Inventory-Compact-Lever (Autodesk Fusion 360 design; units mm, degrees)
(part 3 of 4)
sketch "Restore cam service opening after obsolete bore closure" plane through (23.9, 0, 0) normal (1, 0, 0) x axis (0, 0, -1)
  line L1 (-42.2047, 46.7373) -> (-43.8497, 47.5044)
  line L2 (-40.5875, 45.9133) -> (-42.2047, 46.7373)
  line L3 (-39, 45.0333) -> (-40.5875, 45.9133)
  line L4 (-37.4442, 44.0985) -> (-39, 45.0333)
  line L5 (-35.922, 43.11) -> (-37.4442, 44.0985)
  line L6 (-34.4352, 42.0689) -> (-35.922, 43.11)
  line L7 (-32.9856, 40.9766) -> (-34.4352, 42.0689)
  line L8 (-31.575, 39.8343) -> (-32.9856, 40.9766)
  line L9 (-30.2052, 38.6435) -> (-31.575, 39.8343)
  line L10 (-28.8778, 37.4057) -> (-30.2052, 38.6435)
  line L11 (-27.5943, 36.1222) -> (-28.8778, 37.4057)
  line L12 (-26.3565, 34.7948) -> (-27.5943, 36.1222)
  line L13 (-25.1657, 33.425) -> (-26.3565, 34.7948)
  line L14 (-24.0234, 32.0144) -> (-25.1657, 33.425)
  line L15 (-22.9311, 30.5648) -> (-24.0234, 32.0144)
  line L16 (-21.89, 29.078) -> (-22.9311, 30.5648)
  line L17 (-20.9015, 27.5558) -> (-21.89, 29.078)
  line L18 (-19.9667, 26) -> (-20.9015, 27.5558)
  line L19 (-19.0867, 24.4125) -> (-19.9667, 26)
  line L20 (-18.2627, 22.7953) -> (-19.0867, 24.4125)
  line L21 (-17.4956, 21.1503) -> (-18.2627, 22.7953)
  line L22 (-16.7864, 19.4795) -> (-17.4956, 21.1503)
  line L23 (-16.136, 17.785) -> (-16.7864, 19.4795)
  line L24 (-15.5451, 16.0689) -> (-16.136, 17.785)
  line L25 (-15.0144, 14.3331) -> (-15.5451, 16.0689)
  line L26 (-14.5446, 12.5799) -> (-15.0144, 14.3331)
  line L27 (-14.1363, 10.8114) -> (-14.5446, 12.5799)
  line L28 (-13.79, 9.0297) -> (-14.1363, 10.8114)
  line L29 (-13.5061, 7.237) -> (-13.79, 9.0297)
  line L30 (-13.2849, 5.4355) -> (-13.5061, 7.237)
  line L31 (-13.1267, 3.6273) -> (-13.2849, 5.4355)
  line L32 (-13.0317, 1.8148) -> (-13.1267, 3.6273)
  line L33 (-13, 0) -> (-13.0317, 1.8148)
  line L34 (-13.0317, -1.8148) -> (-13, 0)
  line L35 (-13.1267, -3.6273) -> (-13.0317, -1.8148)
  line L36 (-13.2849, -5.4355) -> (-13.1267, -3.6273)
  line L37 (-13.5061, -7.237) -> (-13.2849, -5.4355)
  line L38 (-13.79, -9.0297) -> (-13.5061, -7.237)
  line L39 (-14.1363, -10.8114) -> (-13.79, -9.0297)
  line L40 (-14.5446, -12.5799) -> (-14.1363, -10.8114)
  line L41 (-15.0144, -14.3331) -> (-14.5446, -12.5799)
  line L42 (-15.5451, -16.0689) -> (-15.0144, -14.3331)
  line L43 (-16.136, -17.785) -> (-15.5451, -16.0689)
  line L44 (-16.7864, -19.4795) -> (-16.136, -17.785)
  line L45 (-17.4956, -21.1503) -> (-16.7864, -19.4795)
  line L46 (-18.2627, -22.7953) -> (-17.4956, -21.1503)
  line L47 (-19.0867, -24.4125) -> (-18.2627, -22.7953)
  line L48 (-19.9667, -26) -> (-19.0867, -24.4125)
  line L49 (-20.9015, -27.5558) -> (-19.9667, -26)
  line L50 (-21.89, -29.078) -> (-20.9015, -27.5558)
  line L51 (-22.9311, -30.5648) -> (-21.89, -29.078)
  line L52 (-24.0234, -32.0144) -> (-22.9311, -30.5648)
  line L53 (-25.1657, -33.425) -> (-24.0234, -32.0144)
  line L54 (-26.3565, -34.7948) -> (-25.1657, -33.425)
  line L55 (-27.5943, -36.1222) -> (-26.3565, -34.7948)
  line L56 (-28.8778, -37.4057) -> (-27.5943, -36.1222)
  line L57 (-30.2052, -38.6435) -> (-28.8778, -37.4057)
  line L58 (-31.575, -39.8343) -> (-30.2052, -38.6435)
  line L59 (-32.9856, -40.9766) -> (-31.575, -39.8343)
  line L60 (-34.4352, -42.0689) -> (-32.9856, -40.9766)
  line L61 (-35.922, -43.11) -> (-34.4352, -42.0689)
  line L62 (-37.4442, -44.0985) -> (-35.922, -43.11)
  line L63 (-39, -45.0333) -> (-37.4442, -44.0985)
  line L64 (-40.5875, -45.9133) -> (-39, -45.0333)
  line L65 (-42.2047, -46.7373) -> (-40.5875, -45.9133)
  line L66 (-43.8497, -47.5044) -> (-42.2047, -46.7373)
  line L67 (-54.4248, -23.7522) -> (-43.8497, -47.5044)
  line L68 (-53.6024, -23.3686) -> (-54.4248, -23.7522)
  line L69 (-52.7937, -22.9566) -> (-53.6024, -23.3686)
  line L70 (-52, -22.5167) -> (-52.7937, -22.9566)
  line L71 (-51.2221, -22.0493) -> (-52, -22.5167)
  line L72 (-50.461, -21.555) -> (-51.2221, -22.0493)
  line L73 (-49.7176, -21.0344) -> (-50.461, -21.555)
  line L74 (-48.9928, -20.4883) -> (-49.7176, -21.0344)
  line L75 (-48.2875, -19.9172) -> (-48.9928, -20.4883)
  line L76 (-47.6026, -19.3218) -> (-48.2875, -19.9172)
  line L77 (-46.9389, -18.7028) -> (-47.6026, -19.3218)
  line L78 (-46.2972, -18.0611) -> (-46.9389, -18.7028)
  line L79 (-45.6782, -17.3974) -> (-46.2972, -18.0611)
  line L80 (-45.0828, -16.7125) -> (-45.6782, -17.3974)
  line L81 (-44.5117, -16.0072) -> (-45.0828, -16.7125)
  line L82 (-43.9656, -15.2824) -> (-44.5117, -16.0072)
  line L83 (-43.445, -14.539) -> (-43.9656, -15.2824)
  line L84 (-42.9507, -13.7779) -> (-43.445, -14.539)
  line L85 (-42.4833, -13) -> (-42.9507, -13.7779)
  line L86 (-42.0434, -12.2063) -> (-42.4833, -13)
  line L87 (-41.6314, -11.3976) -> (-42.0434, -12.2063)
  line L88 (-41.2478, -10.5752) -> (-41.6314, -11.3976)
  line L89 (-40.8932, -9.7398) -> (-41.2478, -10.5752)
  line L90 (-40.568, -8.8925) -> (-40.8932, -9.7398)
  line L91 (-40.2725, -8.0344) -> (-40.568, -8.8925)
  line L92 (-40.0072, -7.1666) -> (-40.2725, -8.0344)
  line L93 (-39.7723, -6.29) -> (-40.0072, -7.1666)
  line L94 (-39.5682, -5.4057) -> (-39.7723, -6.29)
  line L95 (-39.395, -4.5149) -> (-39.5682, -5.4057)
  line L96 (-39.253, -3.6185) -> (-39.395, -4.5149)
  line L97 (-39.1424, -2.7177) -> (-39.253, -3.6185)
  line L98 (-39.0633, -1.8137) -> (-39.1424, -2.7177)
  line L99 (-39.0158, -0.9074) -> (-39.0633, -1.8137)
  line L100 (-39, 0) -> (-39.0158, -0.9074)
  line L101 (-39.0158, 0.9074) -> (-39, 0)
  line L102 (-39.0633, 1.8137) -> (-39.0158, 0.9074)
  line L103 (-39.1424, 2.7177) -> (-39.0633, 1.8137)
  line L104 (-39.253, 3.6185) -> (-39.1424, 2.7177)
  line L105 (-39.395, 4.5149) -> (-39.253, 3.6185)
  line L106 (-39.5682, 5.4057) -> (-39.395, 4.5149)
  line L107 (-39.7723, 6.29) -> (-39.5682, 5.4057)
  line L108 (-40.0072, 7.1666) -> (-39.7723, 6.29)
  line L109 (-40.2725, 8.0344) -> (-40.0072, 7.1666)
  line L110 (-40.568, 8.8925) -> (-40.2725, 8.0344)
  line L111 (-40.8932, 9.7398) -> (-40.568, 8.8925)
  line L112 (-41.2478, 10.5752) -> (-40.8932, 9.7398)
  line L113 (-41.6314, 11.3976) -> (-41.2478, 10.5752)
  line L114 (-42.0434, 12.2063) -> (-41.6314, 11.3976)
  line L115 (-42.4833, 13) -> (-42.0434, 12.2063)
  line L116 (-42.9507, 13.7779) -> (-42.4833, 13)
  line L117 (-43.445, 14.539) -> (-42.9507, 13.7779)
  line L118 (-43.9656, 15.2824) -> (-43.445, 14.539)
  line L119 (-44.5117, 16.0072) -> (-43.9656, 15.2824)
  line L120 (-45.0828, 16.7125) -> (-44.5117, 16.0072)
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extrude "Extrude47" cut sketch "Restore cam service opening after obsolete bore closure" along normal blind 12.2
work_plane "WorkPlane48" AlongDistance -15.4 ExtraOffset 0
sketch "Fill former M5 stop nut pocket" plane through (-15.4, 0, 0) normal (1, 0, 0) x axis (0, 0, -1)
  circle C1 centre (-79.6754, -33.9652) radius 4.9
extrude "Extrude48" add sketch "Fill former M5 stop nut pocket" along normal blind 6.4
work_plane "WorkPlane49" AlongDistance -36 ExtraOffset 0
sketch "Fill former M5 stop bore" plane through (-36, 0, 0) normal (1, 0, 0) x axis (0, 0, -1)
  circle C1 centre (-79.6754, -33.9652) radius 2.71
extrude "Extrude49" add sketch "Fill former M5 stop bore" along normal blind 27
work_plane "WorkPlane50" AlongDistance -36.1 ExtraOffset 0
sketch "M3 stop reinforcement bore" plane through (-36.1, 0, 0) normal (1, 0, 0) x axis (0, 0, -1)
  circle C1 centre (-79.6754, -33.9652) radius 1.7
extrude "Extrude50" cut sketch "M3 stop reinforcement bore" along normal blind 27.2
work_plane "WorkPlane51" AlongDistance -13.5 ExtraOffset 0
sketch "Captive M3 locknut stop pocket" plane through (-13.5, 0, 0) normal (1, 0, 0) x axis (0, 0, -1)
  line L1 (-82.5754, -32.2908) -> (-79.6754, -30.6165)
  line L2 (-82.5754, -35.6395) -> (-82.5754, -32.2908)
  line L3 (-79.6754, -37.3138) -> (-82.5754, -35.6395)
  line L4 (-76.7754, -35.6395) -> (-79.6754, -37.3138)
  line L5 (-76.7754, -32.2908) -> (-76.7754, -35.6395)
  line L6 (-79.6754, -30.6165) -> (-76.7754, -32.2908)
extrude "Extrude51" cut sketch "Captive M3 locknut stop pocket" along normal blind 4.6
work_plane "WorkPlane52" AlongDistance -15.4 ExtraOffset 0
sketch "Fill former M5 stop nut pocket (1)" plane through (-15.4, 0, 0) normal (1, 0, 0) x axis (0, 0, -1)
  circle C1 centre (-79.6754, 33.9652) radius 4.9
extrude "Extrude52" add sketch "Fill former M5 stop nut pocket (1)" along normal blind 6.4
work_plane "WorkPlane53" AlongDistance -36 ExtraOffset 0
sketch "Fill former M5 stop bore (1)" plane through (-36, 0, 0) normal (1, 0, 0) x axis (0, 0, -1)
  circle C1 centre (-79.6754, 33.9652) radius 2.71
extrude "Extrude53" add sketch "Fill former M5 stop bore (1)" along normal blind 27
work_plane "WorkPlane54" AlongDistance -36.1 ExtraOffset 0
sketch "M3 stop reinforcement bore (1)" plane through (-36.1, 0, 0) normal (1, 0, 0) x axis (0, 0, -1)
  circle C1 centre (-79.6754, 33.9652) radius 1.7
extrude "Extrude54" cut sketch "M3 stop reinforcement bore (1)" along normal blind 27.2
work_plane "WorkPlane55" AlongDistance -13.5 ExtraOffset 0
sketch "Captive M3 locknut stop pocket (1)" plane through (-13.5, 0, 0) normal (1, 0, 0) x axis (0, 0, -1)
  line L1 (-82.5754, 35.6395) -> (-79.6754, 37.3138)
  line L2 (-82.5754, 32.2908) -> (-82.5754, 35.6395)
  line L3 (-79.6754, 30.6165) -> (-82.5754, 32.2908)
  line L4 (-76.7754, 32.2908) -> (-79.6754, 30.6165)
  line L5 (-76.7754, 35.6395) -> (-76.7754, 32.2908)
  line L6 (-79.6754, 37.3138) -> (-76.7754, 35.6395)
extrude "Extrude55" cut sketch "Captive M3 locknut stop pocket (1)" along normal blind 4.6
work_plane "WorkPlane56" AlongDistance -17.5 ExtraOffset 0
sketch "Recess M3 locknut to keep bolt inside stop" plane through (-17.5, 0, 0) normal (1, 0, 0) x axis (0, 0, -1)
  line L1 (-82.5754, -32.2908) -> (-79.6754, -30.6165)
  line L2 (-82.5754, -35.6395) -> (-82.5754, -32.2908)
  line L3 (-79.6754, -37.3138) -> (-82.5754, -35.6395)
  line L4 (-76.7754, -35.6395) -> (-79.6754, -37.3138)
  line L5 (-76.7754, -32.2908) -> (-76.7754, -35.6395)
  line L6 (-79.6754, -30.6165) -> (-76.7754, -32.2908)
extrude "Extrude56" cut sketch "Recess M3 locknut to keep bolt inside stop" along normal blind 4.01
work_plane "WorkPlane57" AlongDistance -17.5 ExtraOffset 0
sketch "Recess M3 locknut to keep bolt inside stop (1)" plane through (-17.5, 0, 0) normal (1, 0, 0) x axis (0, 0, -1)
  line L1 (-82.5754, 35.6395) -> (-79.6754, 37.3138)
  line L2 (-82.5754, 32.2908) -> (-82.5754, 35.6395)
  line L3 (-79.6754, 30.6165) -> (-82.5754, 32.2908)
  line L4 (-76.7754, 32.2908) -> (-79.6754, 30.6165)
  line L5 (-76.7754, 35.6395) -> (-76.7754, 32.2908)
  line L6 (-79.6754, 37.3138) -> (-76.7754, 35.6395)
extrude "Extrude57" cut sketch "Recess M3 locknut to keep bolt inside stop (1)" along normal blind 4.01
work_plane "WorkPlane6" AlongDistance -7.2 ExtraOffset 0
sketch "Upright socket roof 45 degrees" plane through (0, -7.2, 0) normal (0, 1, 0) x axis (1, 0, 0)
  line L1 (-7.2, -196) -> (0, -196)
  line L2 (0, -203.2) -> (-7.2, -196)
  line L3 (0, -196) -> (0, -203.2)
extrude "Extrude5" cut sketch "Upright socket roof 45 degrees" along normal blind 14.4
work_plane "WorkPlane8" AlongDistance -7.2 ExtraOffset 0
sketch "Upright socket roof 45 degrees" plane through (0, -7.2, 0) normal (0, 1, 0) x axis (1, 0, 0)
  line L1 (7.2, -196) -> (0, -196)
  line L2 (0, -203.2) -> (7.2, -196)
  line L3 (0, -196) -> (0, -203.2)
extrude "Extrude7" cut sketch "Upright socket roof 45 degrees" along normal blind 14.4
work_plane "WorkPlane58" AlongDistance -36 ExtraOffset 0
sketch "Stock M5x14 mounting seat Z64" plane through (-36, 0, 0) normal (1, 0, 0) x axis (0, 0, -1)
  line L1 (-63, -70) -> (-63, -95)
  line L2 (-64, -70) -> (-63, -70)
  line L3 (-64, -95) -> (-64, -70)
  line L4 (-63, -95) -> (-64, -95)
extrude "Extrude58" add sketch "Stock M5x14 mounting seat Z64" along normal blind 12
work_plane "WorkPlane59" AlongDistance 62.9 ExtraOffset 0
sketch "Continue rail clearance through new seat" plane through (0, 0, 62.9) normal (0, 0, 1) x axis (1, 0, 0)
  circle C1 centre (-30, -85) radius 2.7
extrude "Extrude59" cut sketch "Continue rail clearance through new seat" along normal blind 1.2
work_plane "WorkPlane1" AlongDistance 50 ExtraOffset 0
sketch "Rail M5x14 DIN912 (-30, -1)" plane through (0, 0, 50) normal (0, 0, 1) x axis (1, 0, 0)
  circle C1 centre (-30, -85) radius 2.5
extrude "Extrude1" new body sketch "Rail M5x14 DIN912 (-30, -1)" along normal blind 14 bodies "HARDWARE Rail M5x14 DIN912 (-30, -1)"
work_plane "WorkPlane2" AlongDistance 64 ExtraOffset 0
sketch "Button head" plane through (0, 0, 64) normal (0, 0, 1) x axis (1, 0, 0)
  circle C1 centre (-30, -85) radius 4.25
extrude "Extrude2" add sketch "Button head" along normal blind 5
work_plane "WorkPlane60" AlongDistance -36 ExtraOffset 0
sketch "Stock M5x14 mounting seat Z64 (1)" plane through (-36, 0, 0) normal (1, 0, 0) x axis (0, 0, -1)
  line L1 (-63, 95) -> (-63, 70)
  line L2 (-64, 95) -> (-63, 95)
  line L3 (-64, 70) -> (-64, 95)
  line L4 (-63, 70) -> (-64, 70)
extrude "Extrude60" add sketch "Stock M5x14 mounting seat Z64 (1)" along normal blind 12
work_plane "WorkPlane61" AlongDistance 62.9 ExtraOffset 0
sketch "Continue rail clearance through new seat (1)" plane through (0, 0, 62.9) normal (0, 0, 1) x axis (1, 0, 0)
  circle C1 centre (-30, 85) radius 2.7
extrude "Extrude61" cut sketch "Continue rail clearance through new seat (1)" along normal blind 1.2
work_plane "WorkPlane1" AlongDistance 50 ExtraOffset 0
sketch "Rail M5x14 DIN912 (-30, 1)" plane through (0, 0, 50) normal (0, 0, 1) x axis (1, 0, 0)
  circle C1 centre (-30, 85) radius 2.5
extrude "Extrude1" new body sketch "Rail M5x14 DIN912 (-30, 1)" along normal blind 14 bodies "HARDWARE Rail M5x14 DIN912 (-30, 1)"
work_plane "WorkPlane2" AlongDistance 64 ExtraOffset 0
sketch "Button head" plane through (0, 0, 64) normal (0, 0, 1) x axis (1, 0, 0)
  circle C1 centre (-30, 85) radius 4.25
extrude "Extrude2" add sketch "Button head" along normal blind 5
work_plane "WorkPlane62" AlongDistance -36 ExtraOffset 0
sketch "Close obsolete long pivot screw hole" plane through (-36, 0, 0) normal (1, 0, 0) x axis (0, 0, -1)
  circle C1 centre (-12, -35) radius 1.71
extrude "Extrude62" add sketch "Close obsolete long pivot screw hole" along normal blind 12
work_plane "WorkPlane63" AlongDistance -26 ExtraOffset 0
sketch "Blind captive printed pivot seat" plane through (-26, 0, 0) normal (1, 0, 0) x axis (0, 0, -1)
  circle C1 centre (-12, -35) radius 4.15
extrude "Extrude63" cut sketch "Blind captive printed pivot seat" along normal blind 2.1
work_plane "WorkPlane48" AlongDistance 24 ExtraOffset 0
sketch "Stock M5x14 mounting seat Z64" plane through (24, 0, 0) normal (1, 0, 0) x axis (0, 0, -1)
  line L1 (-63, -70) -> (-63, -95)
  line L2 (-64, -70) -> (-63, -70)
  line L3 (-64, -95) -> (-64, -70)
  line L4 (-63, -95) -> (-64, -95)
extrude "Extrude48" add sketch "Stock M5x14 mounting seat Z64" along normal blind 12
work_plane "WorkPlane49" AlongDistance 62.9 ExtraOffset 0
sketch "Continue rail clearance through new seat" plane through (0, 0, 62.9) normal (0, 0, 1) x axis (1, 0, 0)
  circle C1 centre (30, -85) radius 2.7
extrude "Extrude49" cut sketch "Continue rail clearance through new seat" along normal blind 1.2
work_plane "WorkPlane1" AlongDistance 50 ExtraOffset 0
sketch "Rail M5x14 DIN912 (30, -1)" plane through (0, 0, 50) normal (0, 0, 1) x axis (1, 0, 0)
  circle C1 centre (30, -85) radius 2.5
extrude "Extrude1" new body sketch "Rail M5x14 DIN912 (30, -1)" along normal blind 14 bodies "HARDWARE Rail M5x14 DIN912 (30, -1)"
work_plane "WorkPlane2" AlongDistance 64 ExtraOffset 0
sketch "Button head" plane through (0, 0, 64) normal (0, 0, 1) x axis (1, 0, 0)
  circle C1 centre (30, -85) radius 4.25
extrude "Extrude2" add sketch "Button head" along normal blind 5
work_plane "WorkPlane50" AlongDistance 24 ExtraOffset 0
sketch "Stock M5x14 mounting seat Z64 (1)" plane through (24, 0, 0) normal (1, 0, 0) x axis (0, 0, -1)
  line L1 (-63, 95) -> (-63, 70)
  line L2 (-64, 95) -> (-63, 95)
  line L3 (-64, 70) -> (-64, 95)
  line L4 (-63, 70) -> (-64, 70)
extrude "Extrude50" add sketch "Stock M5x14 mounting seat Z64 (1)" along normal blind 12
work_plane "WorkPlane51" AlongDistance 62.9 ExtraOffset 0
sketch "Continue rail clearance through new seat (1)" plane through (0, 0, 62.9) normal (0, 0, 1) x axis (1, 0, 0)
  circle C1 centre (30, 85) radius 2.7
extrude "Extrude51" cut sketch "Continue rail clearance through new seat (1)" along normal blind 1.2
work_plane "WorkPlane1" AlongDistance 50 ExtraOffset 0
sketch "Rail M5x14 DIN912 (30, 1)" plane through (0, 0, 50) normal (0, 0, 1) x axis (1, 0, 0)
  circle C1 centre (30, 85) radius 2.5
extrude "Extrude1" new body sketch "Rail M5x14 DIN912 (30, 1)" along normal blind 14 bodies "HARDWARE Rail M5x14 DIN912 (30, 1)"
work_plane "WorkPlane2" AlongDistance 64 ExtraOffset 0
sketch "Button head" plane through (0, 0, 64) normal (0, 0, 1) x axis (1, 0, 0)
  circle C1 centre (30, 85) radius 4.25
extrude "Extrude2" add sketch "Button head" along normal blind 5
work_plane "WorkPlane52" AlongDistance 24 ExtraOffset 0
sketch "Close obsolete long pivot screw hole" plane through (24, 0, 0) normal (1, 0, 0) x axis (0, 0, -1)
  circle C1 centre (-12, -35) radius 1.71
extrude "Extrude52" add sketch "Close obsolete long pivot screw hole" along normal blind 12
work_plane "WorkPlane53" AlongDistance 23.9 ExtraOffset 0
sketch "Blind captive printed pivot seat" plane through (23.9, 0, 0) normal (1, 0, 0) x axis (0, 0, -1)
  circle C1 centre (-12, -35) radius 4.15
extrude "Extrude53" cut sketch "Blind captive printed pivot seat" along normal blind 2.1
work_plane "WorkPlane1" AlongDistance -25.85 ExtraOffset 0
sketch "Captured axle 0.3 mm total end clearance" plane through (-25.85, 0, 0) normal (1, 0, 0) x axis (0, 0, -1)
  circle C1 centre (-12, -35) radius 4
extrude "Extrude1" new body sketch "Captured axle 0.3 mm total end clearance" along normal blind 51.7 bodies "P25 Captured printed pivot lower half"
work_plane "WorkPlane2" AlongDistance -26 ExtraOffset 0
sketch "Longitudinal flat print face" plane through (-26, 0, 0) normal (1, 0, 0) x axis (0, 0, -1)
  line L1 (-7, -30) -> (-7, -35)
  line L2 (-17, -30) -> (-7, -30)
  line L3 (-17, -35) -> (-17, -30)
  line L4 (-7, -35) -> (-17, -35)
extrude "Extrude2" cut sketch "Longitudinal flat print face" along normal blind 52
work_plane "WorkPlane1" AlongDistance -25.85 ExtraOffset 0
sketch "Captured axle 0.3 mm total end clearance" plane through (-25.85, 0, 0) normal (1, 0, 0) x axis (0, 0, -1)
  circle C1 centre (-12, -35) radius 4
extrude "Extrude1" new body sketch "Captured axle 0.3 mm total end clearance" along normal blind 51.7 bodies "P26 Captured printed pivot upper half"
work_plane "WorkPlane2" AlongDistance -26 ExtraOffset 0
sketch "Longitudinal flat print face" plane through (-26, 0, 0) normal (1, 0, 0) x axis (0, 0, -1)
  line L1 (-7, -35) -> (-7, -40)
  line L2 (-17, -35) -> (-7, -35)
  line L3 (-17, -40) -> (-17, -35)
  line L4 (-7, -40) -> (-17, -40)
extrude "Extrude2" cut sketch "Longitudinal flat print face" along normal blind 52
work_plane "WorkPlane9" AlongDistance 9 ExtraOffset 0
sketch "Recess for stocked M3x20 grip screw" plane through (9, 0, 0) normal (1, 0, 0) x axis (0, 0, -1)
  circle C1 centre (-180, 0) radius 3.1
extrude "Extrude8" cut sketch "Recess for stocked M3x20 grip screw" along normal blind 3.6
work_plane "WorkPlane1" AlongDistance -11 ExtraOffset 0
sketch "Grip M3x20 cap head 180" plane through (-11, 0, 0) normal (1, 0, 0) x axis (0, 0, -1)
  circle C1 centre (-180, 0) radius 1.5
extrude "Extrude1" new body sketch "Grip M3x20 cap head 180" along normal blind 20 bodies "HARDWARE Grip M3x20 cap head 180"
work_plane "WorkPlane2" AlongDistance 9 ExtraOffset 0
sketch "Button head" plane through (9, 0, 0) normal (1, 0, 0) x axis (0, 0, -1)
  circle C1 centre (-180, 0) radius 2.75
extrude "Extrude2" add sketch "Button head" along normal blind 3
work_plane "WorkPlane10" AlongDistance 9 ExtraOffset 0
sketch "Recess for stocked M3x20 grip screw (1)" plane through (9, 0, 0) normal (1, 0, 0) x axis (0, 0, -1)
  circle C1 centre (-190, 0) radius 3.1
extrude "Extrude9" cut sketch "Recess for stocked M3x20 grip screw (1)" along normal blind 3.6
work_plane "WorkPlane1" AlongDistance -11 ExtraOffset 0
sketch "Grip M3x20 cap head 190" plane through (-11, 0, 0) normal (1, 0, 0) x axis (0, 0, -1)
  circle C1 centre (-190, 0) radius 1.5
extrude "Extrude1" new body sketch "Grip M3x20 cap head 190" along normal blind 20 bodies "HARDWARE Grip M3x20 cap head 190"
work_plane "WorkPlane2" AlongDistance 9 ExtraOffset 0
sketch "Button head" plane through (9, 0, 0) normal (1, 0, 0) x axis (0, 0, -1)
  circle C1 centre (-190, 0) radius 2.75
extrude "Extrude2" add sketch "Button head" along normal blind 3
work_plane "WorkPlane64" AlongDistance -36.1 ExtraOffset 0
sketch "Stock M3x20 stop recessed cap head" plane through (-36.1, 0, 0) normal (1, 0, 0) x axis (0, 0, -1)
  circle C1 centre (-79.6754, -33.9652) radius 3.1
extrude "Extrude64" cut sketch "Stock M3x20 stop recessed cap head" along normal blind 4.6
work_plane "WorkPlane1" AlongDistance -31.5 ExtraOffset 0
sketch "Stop M3x20 cap head -1" plane through (-31.5, 0, 0) normal (1, 0, 0) x axis (0, 0, -1)
  circle C1 centre (-79.6754, -33.9652) radius 1.5
extrude "Extrude1" new body sketch "Stop M3x20 cap head -1" along normal blind 20 bodies "HARDWARE Stop M3x20 cap head -1"
work_plane "WorkPlane2" AlongDistance -34.5 ExtraOffset 0
sketch "Button head" plane through (-34.5, 0, 0) normal (1, 0, 0) x axis (0, 0, -1)
  circle C1 centre (-79.6754, -33.9652) radius 2.75
extrude "Extrude2" add sketch "Button head" along normal blind 3
work_plane "WorkPlane1" AlongDistance -17.5 ExtraOffset 0
sketch "Stop M3 plain captive nut -1" plane through (-17.5, 0, 0) normal (1, 0, 0) x axis (0, 0, -1)
  line L1 (-82.4254, -32.3774) -> (-79.6754, -30.7897)
  line L2 (-82.4254, -35.5529) -> (-82.4254, -32.3774)
  line L3 (-79.6754, -37.1406) -> (-82.4254, -35.5529)
  line L4 (-76.9254, -35.5529) -> (-79.6754, -37.1406)
  line L5 (-76.9254, -32.3774) -> (-76.9254, -35.5529)
  line L6 (-79.6754, -30.7897) -> (-76.9254, -32.3774)
extrude "Extrude1" new body sketch "Stop M3 plain captive nut -1" along normal blind 2.4 bodies "HARDWARE Stop M3 plain captive nut -1"
work_plane "WorkPlane2" AlongDistance -17.6 ExtraOffset 0
sketch "Thread envelope" plane through (-17.6, 0, 0) normal (1, 0, 0) x axis (0, 0, -1)
  circle C1 centre (-79.6754, -33.9652) radius 1.5
extrude "Extrude2" cut sketch "Thread envelope" along normal blind 2.6
work_plane "WorkPlane65" AlongDistance -36.1 ExtraOffset 0
sketch "Stock M3x20 stop recessed cap head (1)" plane through (-36.1, 0, 0) normal (1, 0, 0) x axis (0, 0, -1)
  circle C1 centre (-79.6754, 33.9652) radius 3.1
extrude "Extrude65" cut sketch "Stock M3x20 stop recessed cap head (1)" along normal blind 4.6
work_plane "WorkPlane1" AlongDistance -31.5 ExtraOffset 0
sketch "Stop M3x20 cap head 1" plane through (-31.5, 0, 0) normal (1, 0, 0) x axis (0, 0, -1)
  circle C1 centre (-79.6754, 33.9652) radius 1.5
extrude "Extrude1" new body sketch "Stop M3x20 cap head 1" along normal blind 20 bodies "HARDWARE Stop M3x20 cap head 1"
work_plane "WorkPlane2" AlongDistance -34.5 ExtraOffset 0
sketch "Button head" plane through (-34.5, 0, 0) normal (1, 0, 0) x axis (0, 0, -1)
  circle C1 centre (-79.6754, 33.9652) radius 2.75
extrude "Extrude2" add sketch "Button head" along normal blind 3
work_plane "WorkPlane1" AlongDistance -17.5 ExtraOffset 0
sketch "Stop M3 plain captive nut 1" plane through (-17.5, 0, 0) normal (1, 0, 0) x axis (0, 0, -1)
  line L1 (-82.4254, 35.5529) -> (-79.6754, 37.1406)
  line L2 (-82.4254, 32.3774) -> (-82.4254, 35.5529)
  line L3 (-79.6754, 30.7897) -> (-82.4254, 32.3774)
  line L4 (-76.9254, 32.3774) -> (-79.6754, 30.7897)
  line L5 (-76.9254, 35.5529) -> (-76.9254, 32.3774)
  line L6 (-79.6754, 37.1406) -> (-76.9254, 35.5529)
extrude "Extrude1" new body sketch "Stop M3 plain captive nut 1" along normal blind 2.4 bodies "HARDWARE Stop M3 plain captive nut 1"
work_plane "WorkPlane2" AlongDistance -17.6 ExtraOffset 0
sketch "Thread envelope" plane through (-17.6, 0, 0) normal (1, 0, 0) x axis (0, 0, -1)
  circle C1 centre (-79.6754, 33.9652) radius 1.5
extrude "Extrude2" cut sketch "Thread envelope" along normal blind 2.6
work_plane "WorkPlane10" AlongDistance 7 ExtraOffset 0
sketch "Bearing inner race support pad" plane through (7, 0, 0) normal (1, 0, 0) x axis (0, 0, -1)
  circle C1 centre (-12, 0) radius 2.4
extrude "Extrude10" add sketch "Bearing inner race support pad" along normal blind 1
work_plane "WorkPlane11" AlongDistance 6.9 ExtraOffset 0
sketch "Preserve roller screw clearance" plane through (6.9, 0, 0) normal (1, 0, 0) x axis (0, 0, -1)
  circle C1 centre (-12, 0) radius 1.7
extrude "Extrude11" cut sketch "Preserve roller screw clearance" along normal blind 1.2
work_plane "WorkPlane12" AlongDistance 16 ExtraOffset 0
sketch "Bearing inner race support pad (1)" plane through (16, 0, 0) normal (1, 0, 0) x axis (0, 0, -1)
  circle C1 centre (-12, 0) radius 2.4
extrude "Extrude12" add sketch "Bearing inner race support pad (1)" along normal blind 1
work_plane "WorkPlane13" AlongDistance 15.9 ExtraOffset 0
sketch "Preserve roller screw clearance (1)" plane through (15.9, 0, 0) normal (1, 0, 0) x axis (0, 0, -1)
  circle C1 centre (-12, 0) radius 1.7
extrude "Extrude13" cut sketch "Preserve roller screw clearance (1)" along normal blind 1.2
work_plane "WorkPlane1" AlongDistance 8 ExtraOffset 0
sketch "Stock 623ZZ envelope 3x10x4" plane through (8, 0, 0) normal (1, 0, 0) x axis (0, 0, -1)
  circle C1 centre (-12, 0) radius 5
extrude "Extrude1" new body sketch "Stock 623ZZ envelope 3x10x4" along normal blind 4 bodies "HARDWARE 623ZZ roller bearing at 8"
work_plane "WorkPlane2" AlongDistance 7.9 ExtraOffset 0
sketch "Bearing inner race bore" plane through (7.9, 0, 0) normal (1, 0, 0) x axis (0, 0, -1)
  circle C1 centre (-12, 0) radius 1.5
extrude "Extrude2" cut sketch "Bearing inner race bore" along normal blind 4.2
work_plane "WorkPlane1" AlongDistance 12 ExtraOffset 0
sketch "Stock 623ZZ envelope 3x10x4" plane through (12, 0, 0) normal (1, 0, 0) x axis (0, 0, -1)
  circle C1 centre (-12, 0) radius 5
extrude "Extrude1" new body sketch "Stock 623ZZ envelope 3x10x4" along normal blind 4 bodies "HARDWARE 623ZZ roller bearing at 12"
work_plane "WorkPlane2" AlongDistance 11.9 ExtraOffset 0
sketch "Bearing inner race bore" plane through (11.9, 0, 0) normal (1, 0, 0) x axis (0, 0, -1)
  circle C1 centre (-12, 0) radius 1.5
extrude "Extrude2" cut sketch "Bearing inner race bore" along normal blind 4.2
work_plane "WorkPlane45" AlongDistance 38 ExtraOffset 0
sketch "Close former long guide bore" plane through (0, 0, 38) normal (0, 0, 1) x axis (1, 0, 0)
  circle C1 centre (5, -55) radius 1.71
extrude "Extrude45" add sketch "Close former long guide bore" along normal blind 21
work_plane "WorkPlane46" AlongDistance 38 ExtraOffset 0
sketch "Close former long guide bore (1)" plane through (0, 0, 38) normal (0, 0, 1) x axis (1, 0, 0)
  circle C1 centre (19, -55) radius 1.71
extrude "Extrude46" add sketch "Close former long guide bore (1)" along normal blind 21
work_plane "WorkPlane47" AlongDistance 38 ExtraOffset 0
sketch "Close obsolete M4 nut pocket" plane through (0, 0, 38) normal (0, 0, 1) x axis (1, 0, 0)
  line L1 (14.1362, -51.3) -> (16.2724, -55)
  line L2 (9.8638, -51.3) -> (14.1362, -51.3)
  line L3 (7.7276, -55) -> (9.8638, -51.3)
  line L4 (9.8638, -58.7) -> (7.7276, -55)
  line L5 (14.1362, -58.7) -> (9.8638, -58.7)
  line L6 (16.2724, -55) -> (14.1362, -58.7)
extrude "Extrude47" add sketch "Close obsolete M4 nut pocket" along normal blind 3.5
work_plane "WorkPlane48" AlongDistance 38 ExtraOffset 0
sketch "Close obsolete M4 adjuster passage" plane through (0, 0, 38) normal (0, 0, 1) x axis (1, 0, 0)
  circle C1 centre (12, -55) radius 2.21
extrude "Extrude48" add sketch "Close obsolete M4 adjuster passage" along normal blind 21
work_plane "WorkPlane49" AlongDistance 37.9 ExtraOffset 0
sketch "M3 preload adjuster passage" plane through (0, 0, 37.9) normal (0, 0, 1) x axis (1, 0, 0)
  circle C1 centre (12, -55) radius 1.7
extrude "Extrude49" cut sketch "M3 preload adjuster passage" along normal blind 21.2
work_plane "WorkPlane50" AlongDistance 37.9 ExtraOffset 0
sketch "M3 preload insert from spring side" plane through (0, 0, 37.9) normal (0, 0, 1) x axis (1, 0, 0)
  circle C1 centre (12, -55) radius 2
extrude "Extrude50" cut sketch "M3 preload insert from spring side" along normal blind 6.9
work_plane "WorkPlane51" AlongDistance 55 ExtraOffset 0
sketch "Recessed preload head and limiter access" plane through (0, 0, 55) normal (0, 0, 1) x axis (1, 0, 0)
  circle C1 centre (12, -55) radius 3.4
extrude "Extrude51" cut sketch "Recessed preload head and limiter access" along normal blind 4.1
work_plane "WorkPlane52" AlongDistance 37.9 ExtraOffset 0
sketch "Short guide M3 insert from underside" plane through (0, 0, 37.9) normal (0, 0, 1) x axis (1, 0, 0)
  circle C1 centre (4, -55) radius 2
extrude "Extrude52" cut sketch "Short guide M3 insert from underside" along normal blind 6.9
work_plane "WorkPlane1" AlongDistance 32 ExtraOffset 0
sketch "Short compression sleeve" plane through (0, 0, 32) normal (0, 0, 1) x axis (1, 0, 0)
  circle C1 centre (4, -55) radius 2.5
extrude "Extrude1" new body sketch "Short compression sleeve" along normal blind 6 bodies "P27 Printed guide sleeve 4"
work_plane "WorkPlane2" AlongDistance 31.9 ExtraOffset 0
sketch "Guide screw bore" plane through (0, 0, 31.9) normal (0, 0, 1) x axis (1, 0, 0)
  circle C1 centre (4, -55) radius 1.65
extrude "Extrude2" cut sketch "Guide screw bore" along normal blind 6.2
work_plane "WorkPlane1" AlongDistance 32 ExtraOffset 0
sketch "Cup guide M3x12 4" plane through (0, 0, 32) normal (0, 0, 1) x axis (1, 0, 0)
  circle C1 centre (4, -55) radius 1.5
extrude "Extrude1" new body sketch "Cup guide M3x12 4" along normal blind 12 bodies "HARDWARE Cup guide M3x12 4"
work_plane "WorkPlane2" AlongDistance 29 ExtraOffset 0
sketch "Button head" plane through (0, 0, 29) normal (0, 0, 1) x axis (1, 0, 0)
  circle C1 centre (4, -55) radius 2.75
extrude "Extrude2" add sketch "Button head" along normal blind 3
work_plane "WorkPlane53" AlongDistance 37.9 ExtraOffset 0
sketch "Short guide M3 insert from underside (1)" plane through (0, 0, 37.9) normal (0, 0, 1) x axis (1, 0, 0)
  circle C1 centre (20, -55) radius 2
extrude "Extrude53" cut sketch "Short guide M3 insert from underside (1)" along normal blind 6.9
work_plane "WorkPlane1" AlongDistance 32 ExtraOffset 0
sketch "Short compression sleeve" plane through (0, 0, 32) normal (0, 0, 1) x axis (1, 0, 0)
  circle C1 centre (20, -55) radius 2.5
extrude "Extrude1" new body sketch "Short compression sleeve" along normal blind 6 bodies "P27 Printed guide sleeve 20"
work_plane "WorkPlane2" AlongDistance 31.9 ExtraOffset 0
sketch "Guide screw bore" plane through (0, 0, 31.9) normal (0, 0, 1) x axis (1, 0, 0)
  circle C1 centre (20, -55) radius 1.65
extrude "Extrude2" cut sketch "Guide screw bore" along normal blind 6.2
work_plane "WorkPlane1" AlongDistance 32 ExtraOffset 0
sketch "Cup guide M3x12 20" plane through (0, 0, 32) normal (0, 0, 1) x axis (1, 0, 0)
  circle C1 centre (20, -55) radius 1.5
extrude "Extrude1" new body sketch "Cup guide M3x12 20" along normal blind 12 bodies "HARDWARE Cup guide M3x12 20"
work_plane "WorkPlane2" AlongDistance 29 ExtraOffset 0
sketch "Button head" plane through (0, 0, 29) normal (0, 0, 1) x axis (1, 0, 0)
  circle C1 centre (20, -55) radius 2.75
extrude "Extrude2" add sketch "Button head" along normal blind 3
work_plane "WorkPlane1" AlongDistance 0.2 ExtraOffset 0
sketch "Wide stock spring seat" plane through (0.2, 0, 0) normal (1, 0, 0) x axis (0, 0, -1)
  line L1 (-35, -49) -> (-35, -61)
  line L2 (-37, -49) -> (-35, -49)
  line L3 (-37, -61) -> (-37, -49)
  line L4 (-35, -61) -> (-37, -61)
extrude "Extrude1" new body sketch "Wide stock spring seat" along normal blind 23.6 bodies "P14 Captive spring cup for 9 mm spring"
work_plane "WorkPlane2" AlongDistance 29 ExtraOffset 0
sketch "Provisional 6 mm spring pilot" plane through (0, 0, 29) normal (0, 0, 1) x axis (1, 0, 0)
  circle C1 centre (12, -55) radius 3
extrude "Extrude2" add sketch "Provisional 6 mm spring pilot" along normal blind 6
work_plane "WorkPlane3" AlongDistance 34.9 ExtraOffset 0
sketch "Printed guide running clearance" plane through (0, 0, 34.9) normal (0, 0, 1) x axis (1, 0, 0)
  circle C1 centre (4, -55) radius 2.7
extrude "Extrude3" cut sketch "Printed guide running clearance" along normal blind 2.2
work_plane "WorkPlane4" AlongDistance 34.9 ExtraOffset 0
sketch "Printed guide running clearance (1)" plane through (0, 0, 34.9) normal (0, 0, 1) x axis (1, 0, 0)
  circle C1 centre (20, -55) radius 2.7
extrude "Extrude4" cut sketch "Printed guide running clearance (1)" along normal blind 2.2
work_plane "WorkPlane1" AlongDistance 55 ExtraOffset 0
sketch "Preserve one mm additional compression limit" plane through (0, 0, 55) normal (0, 0, 1) x axis (1, 0, 0)
  circle C1 centre (12, -55) radius 3.2
extrude "Extrude1" new body sketch "Preserve one mm additional compression limit" along normal blind 2 bodies "P15 Recessed preload limit collar 1 mm"
work_plane "WorkPlane2" AlongDistance 54.9 ExtraOffset 0
sketch "M3 adjuster clearance" plane through (0, 0, 54.9) normal (0, 0, 1) x axis (1, 0, 0)
  circle C1 centre (12, -55) radius 1.7
extrude "Extrude2" cut sketch "M3 adjuster clearance" along normal blind 2.2
work_plane "WorkPlane1" AlongDistance 37 ExtraOffset 0
sketch "Preload M3x20 cap head" plane through (0, 0, 37) normal (0, 0, 1) x axis (1, 0, 0)
  circle C1 centre (12, -55) radius 1.5
extrude "Extrude1" new body sketch "Preload M3x20 cap head" along normal blind 20 bodies "HARDWARE Preload M3x20 cap head"
work_plane "WorkPlane2" AlongDistance 57 ExtraOffset 0
sketch "Button head" plane through (0, 0, 57) normal (0, 0, 1) x axis (1, 0, 0)
  circle C1 centre (12, -55) radius 2.75
extrude "Extrude2" add sketch "Button head" along normal blind 3
work_plane "WorkPlane1" AlongDistance 18 ExtraOffset 0
sketch "Provisional stock spring installed envelope" plane through (0, 0, 18) normal (0, 0, 1) x axis (1, 0, 0)
  circle C1 centre (12, -55) radius 4.5
extrude "Extrude1" new body sketch "Provisional stock spring installed envelope" along normal blind 17 bodies "REFERENCE Stock spring OD9 wire1 free20 - rate and solid height assumed"
work_plane "WorkPlane2" AlongDistance 17.9 ExtraOffset 0
sketch "Stock spring nominal ID7" plane through (0, 0, 17.9) normal (0, 0, 1) x axis (1, 0, 0)
  circle C1 centre (12, -55) radius 3.5
extrude "Extrude2" cut sketch "Stock spring nominal ID7" along normal blind 17.2
work_plane "WorkPlane9" AlongDistance 40.35 ExtraOffset 0
sketch "Remove separate input hub drive stub" plane through (40.35, 0, 0) normal (1, 0, 0) x axis (0, 0, -1)
  line L1 (-53, 12) -> (-53, -12)
  line L2 (-79, 12) -> (-53, 12)
  line L3 (-79, -12) -> (-79, 12)
  line L4 (-53, -12) -> (-79, -12)
extrude "Extrude9" cut sketch "Remove separate input hub drive stub" along normal blind 10.15
work_plane "WorkPlane10" AlongDistance 40.35 ExtraOffset 0
sketch "Integrated compact Oldham input tongue" plane through (40.35, 0, 0) normal (1, 0, 0) x axis (0, 0, -1)
  line L1 (-63, 6.5) -> (-63, -8)
  line L2 (-67, 6.5) -> (-63, 6.5)
  line L3 (-67, -8) -> (-67, 6.5)
  line L4 (-63, -8) -> (-67, -8)
extrude "Extrude10" add sketch "Integrated compact Oldham input tongue" along normal blind 3
work_plane "WorkPlane54" AlongDistance 36 ExtraOffset 0
sketch "Remove long sensor carriage supports" plane through (36, 0, 0) normal (1, 0, 0) x axis (0, 0, -1)
  line L1 (-46, 34) -> (-46, -34)
  line L2 (-84, 34) -> (-46, 34)
  line L3 (-84, -34) -> (-84, 34)
  line L4 (-46, -34) -> (-84, -34)
extrude "Extrude54" cut sketch "Remove long sensor carriage supports" along normal blind 44.1
work_plane "WorkPlane55" AlongDistance 36 ExtraOffset 0
sketch "Compact sensor support" plane through (36, 0, 0) normal (1, 0, 0) x axis (0, 0, -1)
  line L1 (-49, -18) -> (-49, -28)
  line L2 (-81, -18) -> (-49, -18)
  line L3 (-81, -28) -> (-81, -18)
  line L4 (-49, -28) -> (-81, -28)
extrude "Extrude55" add sketch "Compact sensor support" along normal blind 30.15
work_plane "WorkPlane56" AlongDistance -28.1 ExtraOffset 0
sketch "Compact carriage M3 insert" plane through (0, -28.1, 0) normal (0, 1, 0) x axis (1, 0, 0)
  circle C1 centre (60.15, -65) radius 2
extrude "Extrude56" cut sketch "Compact carriage M3 insert" along normal blind 6.8
work_plane "WorkPlane57" AlongDistance 36 ExtraOffset 0
sketch "Compact sensor support (1)" plane through (36, 0, 0) normal (1, 0, 0) x axis (0, 0, -1)
  line L1 (-49, 28) -> (-49, 18)
  line L2 (-81, 28) -> (-49, 28)
  line L3 (-81, 18) -> (-81, 28)
  line L4 (-49, 18) -> (-81, 18)
extrude "Extrude57" add sketch "Compact sensor support (1)" along normal blind 30.15
work_plane "WorkPlane58" AlongDistance 21.3 ExtraOffset 0
sketch "Compact carriage M3 insert (1)" plane through (0, 21.3, 0) normal (0, 1, 0) x axis (1, 0, 0)
  circle C1 centre (60.15, -65) radius 2
extrude "Extrude58" cut sketch "Compact carriage M3 insert (1)" along normal blind 6.8
work_plane "WorkPlane1" AlongDistance 66.15 ExtraOffset 0
sketch "Replaceable compact sensor panel" plane through (66.15, 0, 0) normal (1, 0, 0) x axis (0, 0, -1)
  line L1 (-46, 33) -> (-46, -33)
  line L2 (-84, 33) -> (-46, 33)
  line L3 (-84, -33) -> (-84, 33)
  line L4 (-46, -33) -> (-84, -33)
extrude "Extrude1" new body sketch "Replaceable compact sensor panel" along normal blind 3 bodies "P16 Compact adjustable RK097 mount"
work_plane "WorkPlane2" AlongDistance 54.15 ExtraOffset 0
sketch "Compact sliding ear" plane through (54.15, 0, 0) normal (1, 0, 0) x axis (0, 0, -1)
  line L1 (-58, -28) -> (-58, -33)
  line L2 (-72, -28) -> (-58, -28)
  line L3 (-72, -33) -> (-72, -28)
  line L4 (-58, -33) -> (-72, -33)
extrude "Extrude2" add sketch "Compact sliding ear" along normal blind 12.1
work_plane "WorkPlane3" AlongDistance -33.1 ExtraOffset 0
sketch "Axial adjustment slot" plane through (0, -33.1, 0) normal (0, 1, 0) x axis (1, 0, 0)
  line L1 (65.15, -63.3) -> (55.15, -63.3)
  line L2 (65.15, -66.7) -> (65.15, -63.3)
  line L3 (55.15, -66.7) -> (65.15, -66.7)
  line L4 (55.15, -63.3) -> (55.15, -66.7)
extrude "Extrude3" cut sketch "Axial adjustment slot" along normal blind 5.2
work_plane "WorkPlane4" AlongDistance -33.1 ExtraOffset 0
sketch "Rounded slot end" plane through (0, -33.1, 0) normal (0, 1, 0) x axis (1, 0, 0)
  circle C1 centre (55.15, -65) radius 1.7
extrude "Extrude4" cut sketch "Rounded slot end" along normal blind 5.2
work_plane "WorkPlane5" AlongDistance -33.1 ExtraOffset 0
sketch "Rounded slot end (1)" plane through (0, -33.1, 0) normal (0, 1, 0) x axis (1, 0, 0)
  circle C1 centre (65.15, -65) radius 1.7
extrude "Extrude5" cut sketch "Rounded slot end (1)" along normal blind 5.2
work_plane "WorkPlane1" AlongDistance -33 ExtraOffset 0
sketch "Compact carriage M3x12 -1" plane through (0, -33, 0) normal (0, 1, 0) x axis (1, 0, 0)
  circle C1 centre (60.15, -65) radius 1.5
extrude "Extrude1" new body sketch "Compact carriage M3x12 -1" along normal blind 12 bodies "HARDWARE Compact carriage M3x12 -1"
work_plane "WorkPlane2" AlongDistance -36 ExtraOffset 0
sketch "Button head" plane through (0, -36, 0) normal (0, 1, 0) x axis (1, 0, 0)
  circle C1 centre (60.15, -65) radius 2.75
extrude "Extrude2" add sketch "Button head" along normal blind 3
work_plane "WorkPlane6" AlongDistance 54.15 ExtraOffset 0
sketch "Compact sliding ear (1)" plane through (54.15, 0, 0) normal (1, 0, 0) x axis (0, 0, -1)
  line L1 (-58, 33) -> (-58, 28)
  line L2 (-72, 33) -> (-58, 33)
  line L3 (-72, 28) -> (-72, 33)
  line L4 (-58, 28) -> (-72, 28)
extrude "Extrude6" add sketch "Compact sliding ear (1)" along normal blind 12.1
work_plane "WorkPlane7" AlongDistance 27.9 ExtraOffset 0
sketch "Axial adjustment slot (1)" plane through (0, 27.9, 0) normal (0, 1, 0) x axis (1, 0, 0)
  line L1 (65.15, -63.3) -> (55.15, -63.3)
  line L2 (65.15, -66.7) -> (65.15, -63.3)
  line L3 (55.15, -66.7) -> (65.15, -66.7)
  line L4 (55.15, -63.3) -> (55.15, -66.7)
extrude "Extrude7" cut sketch "Axial adjustment slot (1)" along normal blind 5.2
work_plane "WorkPlane8" AlongDistance 27.9 ExtraOffset 0
sketch "Rounded slot end (2)" plane through (0, 27.9, 0) normal (0, 1, 0) x axis (1, 0, 0)
  circle C1 centre (55.15, -65) radius 1.7
extrude "Extrude8" cut sketch "Rounded slot end (2)" along normal blind 5.2
work_plane "WorkPlane9" AlongDistance 27.9 ExtraOffset 0
sketch "Rounded slot end (3)" plane through (0, 27.9, 0) normal (0, 1, 0) x axis (1, 0, 0)
  circle C1 centre (65.15, -65) radius 1.7
extrude "Extrude9" cut sketch "Rounded slot end (3)" along normal blind 5.2
work_plane "WorkPlane1" AlongDistance 21 ExtraOffset 0
sketch "Compact carriage M3x12 1" plane through (0, 21, 0) normal (0, 1, 0) x axis (1, 0, 0)
  circle C1 centre (60.15, -65) radius 1.5
extrude "Extrude1" new body sketch "Compact carriage M3x12 1" along normal blind 12 bodies "HARDWARE Compact carriage M3x12 1"
work_plane "WorkPlane2" AlongDistance 33 ExtraOffset 0
sketch "Button head" plane through (0, 33, 0) normal (0, 1, 0) x axis (1, 0, 0)
  circle C1 centre (60.15, -65) radius 2.75
extrude "Extrude2" add sketch "Button head" along normal blind 3
work_plane "WorkPlane10" AlongDistance 66.05 ExtraOffset 0
sketch "Provisional M7 sensor bushing opening" plane through (66.05, 0, 0) normal (1, 0, 0) x axis (0, 0, -1)
  circle C1 centre (-65, 0) radius 3.6
extrude "Extrude10" cut sketch "Provisional M7 sensor bushing opening" along normal blind 3.2
work_plane "WorkPlane11" AlongDistance 66.05 ExtraOffset 0
sketch "Sensor body retention option" plane through (66.05, 0, 0) normal (1, 0, 0) x axis (0, 0, -1)
  line L1 (-59, -7) -> (-59, -9)
  line L2 (-71, -7) -> (-59, -7)
  line L3 (-71, -9) -> (-71, -7)
  line L4 (-59, -9) -> (-71, -9)
extrude "Extrude11" cut sketch "Sensor body retention option" along normal blind 3.2
work_plane "WorkPlane12" AlongDistance 66.05 ExtraOffset 0
sketch "Sensor body retention option (1)" plane through (66.05, 0, 0) normal (1, 0, 0) x axis (0, 0, -1)
  line L1 (-59, 9) -> (-59, 7)
  line L2 (-71, 9) -> (-59, 9)
  line L3 (-71, 7) -> (-71, 9)
  line L4 (-59, 7) -> (-71, 7)
extrude "Extrude12" cut sketch "Sensor body retention option (1)" along normal blind 3.2
work_plane "WorkPlane1" AlongDistance 41 ExtraOffset 0
sketch "Compact Oldham disc" plane through (41, 0, 0) normal (1, 0, 0) x axis (0, 0, -1)
  circle C1 centre (-65, 0) radius 12
extrude "Extrude1" new body sketch "Compact Oldham disc" along normal blind 8 bodies "P18 Compact floating coupling disc"
work_plane "WorkPlane2" AlongDistance 40.9 ExtraOffset 0
sketch "Input groove 4.2 mm" plane through (40.9, 0, 0) normal (1, 0, 0) x axis (0, 0, -1)
  line L1 (-62.9, 13) -> (-62.9, -13)
  line L2 (-67.1, 13) -> (-62.9, 13)
  line L3 (-67.1, -13) -> (-67.1, 13)
  line L4 (-62.9, -13) -> (-67.1, -13)
extrude "Extrude2" cut sketch "Input groove 4.2 mm" along normal blind 2.9
work_plane "WorkPlane3" AlongDistance 46.2 ExtraOffset 0
sketch "Output groove 4.2 mm" plane through (46.2, 0, 0) normal (1, 0, 0) x axis (0, 0, -1)
  line L1 (-52, 2.1) -> (-52, -2.1)
  line L2 (-78, 2.1) -> (-52, 2.1)
  line L3 (-78, -2.1) -> (-78, 2.1)
  line L4 (-52, -2.1) -> (-78, -2.1)
extrude "Extrude3" cut sketch "Output groove 4.2 mm" along normal blind 2.9
work_plane "WorkPlane1" AlongDistance 49.65 ExtraOffset 0
sketch "Single split output hub" plane through (49.65, 0, 0) normal (1, 0, 0) x axis (0, 0, -1)
  circle C1 centre (-65, 0) radius 7
extrude "Extrude1" new body sketch "Single split output hub" along normal blind 9 bodies "P19 Compact one-piece sensor clamp"
work_plane "WorkPlane2" AlongDistance 49.65 ExtraOffset 0
sketch "One-screw clamp boss" plane through (49.65, 0, 0) normal (1, 0, 0) x axis (0, 0, -1)
  line L1 (-69, 9) -> (-69, -9)
  line L2 (-78, 9) -> (-69, 9)
  line L3 (-78, -9) -> (-78, 9)
  line L4 (-69, -9) -> (-78, -9)
extrude "Extrude2" add sketch "One-screw clamp boss" along normal blind 9
work_plane "WorkPlane3" AlongDistance 46.65 ExtraOffset 0
sketch "Output drive prongs" plane through (46.65, 0, 0) normal (1, 0, 0) x axis (0, 0, -1)
  line L1 (-57, 2) -> (-57, -2)
  line L2 (-73, 2) -> (-57, 2)
  line L3 (-73, -2) -> (-73, 2)
  line L4 (-57, -2) -> (-73, -2)
extrude "Extrude3" add sketch "Output drive prongs" along normal blind 3.1
work_plane "WorkPlane4" AlongDistance 46.55 ExtraOffset 0
sketch "Provisional 6 mm sensor through socket" plane through (46.55, 0, 0) normal (1, 0, 0) x axis (0, 0, -1)
  circle C1 centre (-65, 0) radius 3.1
extrude "Extrude4" cut sketch "Provisional 6 mm sensor through socket" along normal blind 12.2
work_plane "WorkPlane5" AlongDistance 46.55 ExtraOffset 0
sketch "Elastic clamp split" plane through (46.55, 0, 0) normal (1, 0, 0) x axis (0, 0, -1)
  line L1 (-65, 0.2) -> (-65, -0.2)
  line L2 (-79, 0.2) -> (-65, 0.2)
  line L3 (-79, -0.2) -> (-79, 0.2)
  line L4 (-65, -0.2) -> (-79, -0.2)
extrude "Extrude5" cut sketch "Elastic clamp split" along normal blind 12.2
work_plane "WorkPlane6" AlongDistance -9.1 ExtraOffset 0
sketch "Accessible CNC Kitchen insert pocket" plane through (0, -9.1, 0) normal (0, 1, 0) x axis (1, 0, 0)
  circle C1 centre (54.15, -73) radius 2
extrude "Extrude6" cut sketch "Accessible CNC Kitchen insert pocket" along normal blind 9
work_plane "WorkPlane7" AlongDistance 0.1 ExtraOffset 0
sketch "Clamp screw clearance" plane through (0, 0.1, 0) normal (0, 1, 0) x axis (1, 0, 0)
  circle C1 centre (54.15, -73) radius 1.7
extrude "Extrude7" cut sketch "Clamp screw clearance" along normal blind 9
work_plane "WorkPlane1" AlongDistance -7 ExtraOffset 0
sketch "Compact sensor clamp M3x16" plane through (0, -7, 0) normal (0, 1, 0) x axis (1, 0, 0)
  circle C1 centre (54.15, -73) radius 1.5
extrude "Extrude1" new body sketch "Compact sensor clamp M3x16" along normal blind 16 bodies "HARDWARE Compact sensor clamp M3x16"
work_plane "WorkPlane2" AlongDistance 9 ExtraOffset 0
sketch "Button head" plane through (0, 9, 0) normal (0, 1, 0) x axis (1, 0, 0)
  circle C1 centre (54.15, -73) radius 2.75
extrude "Extrude2" add sketch "Button head" along normal blind 3
work_plane "WorkPlane1" AlongDistance 69.15 ExtraOffset 0
sketch "Unmeasured sensor body" plane through (69.15, 0, 0) normal (1, 0, 0) x axis (0, 0, -1)
  line L1 (-60.25, 4.75) -> (-60.25, -4.75)
  line L2 (-69.75, 4.75) -> (-60.25, 4.75)
  line L3 (-69.75, -4.75) -> (-69.75, 4.75)
  line L4 (-60.25, -4.75) -> (-69.75, -4.75)
extrude "Extrude1" new body sketch "Unmeasured sensor body" along normal blind 14 bodies "REFERENCE RK097 provisional compact envelope - measure before fit"
work_plane "WorkPlane2" AlongDistance 62.15 ExtraOffset 0
sketch "Provisional mounting bushing" plane through (62.15, 0, 0) normal (1, 0, 0) x axis (0, 0, -1)
  circle C1 centre (-65, 0) radius 3.5
extrude "Extrude2" add sketch "Provisional mounting bushing" along normal blind 7
work_plane "WorkPlane3" AlongDistance 50.15 ExtraOffset 0
sketch "Provisional exposed sensor shaft" plane through (50.15, 0, 0) normal (1, 0, 0) x axis (0, 0, -1)
  circle C1 centre (-65, 0) radius 3
extrude "Extrude3" add sketch "Provisional exposed sensor shaft" along normal blind 12
work_plane "WorkPlane1" AlongDistance 65.65 ExtraOffset 0
sketch "RK097 supplied washer ASSUMED" plane through (65.65, 0, 0) normal (1, 0, 0) x axis (0, 0, -1)
  circle C1 centre (-65, 0) radius 6
extrude "Extrude1" new body sketch "RK097 supplied washer ASSUMED" along normal blind 0.5 bodies "HARDWARE RK097 supplied washer ASSUMED"
work_plane "WorkPlane2" AlongDistance 65.55 ExtraOffset 0
sketch "Washer clearance" plane through (65.55, 0, 0) normal (1, 0, 0) x axis (0, 0, -1)
  circle C1 centre (-65, 0) radius 3.6
extrude "Extrude2" cut sketch "Washer clearance" along normal blind 0.7
work_plane "WorkPlane1" AlongDistance 63.65 ExtraOffset 0
sketch "RK097 supplied nut ASSUMED" plane through (63.65, 0, 0) normal (1, 0, 0) x axis (0, 0, -1)
  line L1 (-70.5, 3.1754) -> (-65, 6.3509)
  line L2 (-70.5, -3.1754) -> (-70.5, 3.1754)
  line L3 (-65, -6.3509) -> (-70.5, -3.1754)
  line L4 (-59.5, -3.1754) -> (-65, -6.3509)
  line L5 (-59.5, 3.1754) -> (-59.5, -3.1754)
  line L6 (-65, 6.3509) -> (-59.5, 3.1754)
extrude "Extrude1" new body sketch "RK097 supplied nut ASSUMED" along normal blind 2 bodies "HARDWARE RK097 supplied nut ASSUMED"
work_plane "WorkPlane2" AlongDistance 63.55 ExtraOffset 0
sketch "Thread envelope" plane through (63.55, 0, 0) normal (1, 0, 0) x axis (0, 0, -1)
  circle C1 centre (-65, 0) radius 3.5
extrude "Extrude2" cut sketch "Thread envelope" along normal blind 2.2
work_plane "WorkPlane59" AlongDistance 36 ExtraOffset 0
sketch "Restore cam service path beneath compact rails" plane through (36, 0, 0) normal (1, 0, 0) x axis (0, 0, -1)
  line L1 (-48.9, -18) -> (-48.9, -28)
  line L2 (-56, -18) -> (-48.9, -18)
  line L3 (-56, -28) -> (-56, -18)
  line L4 (-48.9, -28) -> (-56, -28)
extrude "Extrude59" cut sketch "Restore cam service path beneath compact rails" along normal blind 30.25
work_plane "WorkPlane60" AlongDistance 36 ExtraOffset 0
sketch "Restore cam service path beneath compact rails (1)" plane through (36, 0, 0) normal (1, 0, 0) x axis (0, 0, -1)
  line L1 (-48.9, 28) -> (-48.9, 18)
  line L2 (-56, 28) -> (-48.9, 28)
  line L3 (-56, 18) -> (-56, 28)
  line L4 (-48.9, 18) -> (-56, 18)
extrude "Extrude60" cut sketch "Restore cam service path beneath compact rails (1)" along normal blind 30.25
